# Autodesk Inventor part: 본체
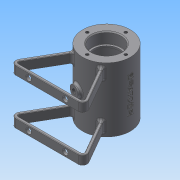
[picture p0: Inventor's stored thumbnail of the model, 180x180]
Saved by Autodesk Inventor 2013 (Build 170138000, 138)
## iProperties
Created: 2016-03
Part Number: 본체
Material: 일반
Document SubType Name: Modeling
Designer: Administrator
Density: 1 g/cm^3
Author: Administrator
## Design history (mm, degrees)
sketch "스케치1"
  geometry: C1 r 26 at (0, 0); 1 further point
  constraints: 1 centre point, 1 coincident
  dimensions: "d0" = 52 diameter of C1
extrude "돌출1" new body sketch "스케치1" stored distance "d1" = 70; taper "d2" = 0 deg
node "작업 평면1"
sketch "스케치3"
  geometry: L1 (0, -65)-(33.934, -65); L2 (0, -65)-(-33.934, -65); L3 (-16.613, -20)-(-38.264, -57.5); L4 (16.613, -20)-(38.264, -57.5); L5 (35.666, -59)-(15.685, -24.392); L6 (-15.685, -24.392)-(-35.666, -59); L7 (-33.934, -62)-(0, -62); L8 (0, -62)-(33.934, -62); L9 (15.685, -24.392)-(14.183, -21.791); L10 (-15.685, -24.392)-(-14.183, -21.791); A1 r 26 centre (0, 0) between (16.613, -20) and (-16.613, -20) reference; A2 r 5 centre (-33.934, -60) between (-38.264, -57.5) and (-33.934, -65); A3 r 5 centre (33.934, -60) between (33.934, -65) and (38.264, -57.5); A4 r 2 centre (-33.934, -60) between (-35.666, -59) and (-33.934, -62); A5 r 2 centre (33.934, -60) between (33.934, -62) and (35.666, -59); A6 r 26 centre (0, 0) between (-16.613, -20) and (-14.183, -21.791); A7 r 26 centre (0, 0) between (14.183, -21.791) and (16.613, -20); 3 further points
  constraints: 20 end point, 14 point on circle, 6 centre point, 4 collinear, 4 point on line, 4 tangent, 1 coincident, 1 equal radius, 4 other
  dimensions: "d33" = 45 vertical distance of point (42.594, -65) L4.start; "d34" = 45 vertical distance of point (-42.594, -65) L3.start; "d37" = 5 radius of A2; "d38" = 3 distance between parallel lines of L4 L5
extrude "돌출2" join sketch "스케치3" distance "d39" = 10; taper "d40" = 0 deg
sketch "스케치4"
  geometry: C1 r 26 at (0, 0) reference; C2 r 16 at (0, 0)
  constraints: 1 centre point, 1 coincident
  dimensions: "d41" = 32 diameter of C2
extrude "돌출3" cut sketch "스케치4" distance "d42" = 12; taper "d43" = 0 deg
sketch "스케치5"
  geometry: C1 r 16 at (0, 0) reference; C2 r 14 at (0, 0)
  constraints: 1 centre point, 1 coincident
  dimensions: "d44" = 28 diameter of C2
extrude "돌출4" cut sketch "스케치5" distance "d45" = 2; taper "d46" = 0 deg
sketch "스케치6"
  geometry: L1 (0, 0)-(0, 21); C1 r 26 at (0, 0) reference
  constraints: 2 end point, 1 coincident, 1 vertical alignment, 2 other
hole "구멍1" sketch "스케치6" at (0, 21) diameter "d48" = 3.242; stored, may be unused: countersink angle "d52" = 90 deg, drill point angle "d54" = 118 deg; dims "d49" = 8, "d50" = 4, "d51" = 2, "d53" = 10
node "작업 평면2"
sketch "스케치7"
  geometry: C1 r 21 at (0, 0); 1 further point
  constraints: 1 centre point, 1 coincident
  dimensions: "d58" = 42 diameter of C1
extrude "돌출5" cut sketch "스케치7" stored distance "d59" = 42; taper "d60" = 0 deg
sketch "스케치8"
  geometry: L1 (0, 0)-(67.868, 0) reference; L2 (67.868, -10)-(0, -10) reference; L3 (33.934, -10)-(33.934, -5); C1 r 3 at (53.934, -5); C2 r 3 at (13.934, -5); 1 further point
  constraints: 2 centre point, 2 end point, 1 midpoint, 1 perpendicular
  dimensions: "d63" = 6 diameter of C1; "d65" = 6 diameter of C2
extrude "돌출6" cut sketch "스케치8" distance "d66" = 20; taper "d67" = 0 deg
node "작업 평면3"
sketch "스케치9"
  geometry: L1 (26, 35)-(-26, 35) reference; L2 (0, 35)-(0, 0); C1 r 5 at (0, 0)
  constraints: 2 end point, 1 centre point, 1 coincident, 1 midpoint, 1 perpendicular
  dimensions: "d69" = 35 distance of L2.start L2.end (derived); "d70" = 10 diameter of C1
extrude "돌출7" join sketch "스케치9" stored distance "d71" = 20; taper "d72" = 0 deg
sketch "스케치10"
  geometry: C1 r 5 at (0, 0) reference
hole "구멍2" sketch "스케치10" at (0, 0) diameter "d73" = 5.188; stored, may be unused: countersink angle "d77" = 90 deg, drill point angle "d79" = 118 deg; dims "d74" = 8, "d75" = 4, "d76" = 2, "d78" = 10
sketch "스케치11"
  geometry: L1 (0, 0)-(0, -44.243); L2 (0, 0)-(-7.506, -28.012)
  constraints: 4 end point, 1 vertical
  dimensions: "d80" = 29 distance of L1.start L2.end; "d81" = 15 deg angle of L1 L2
node "작업 평면4"
sketch "스케치12"
  geometry: C1 r 6 at (0, 0); 1 further point
  constraints: 1 centre point, 1 coincident
  dimensions: "d82" = 12 diameter of C1
extrude "돌출8" join sketch "스케치12" stored distance "d83" = 20; taper "d84" = 0 deg
sketch "스케치13"
  geometry: C1 r 6 at (0, 0) reference
hole "구멍3" sketch "스케치13" at (0, 0) diameter "d85" = 5.188; stored, may be unused: countersink angle "d89" = 90 deg, drill point angle "d91" = 118 deg; dims "d86" = 8, "d87" = 4, "d88" = 2, "d90" = 10
node "작업 평면5"
sketch "스케치14"
  geometry: L1 (26, 35)-(-26, 35) reference; 2 further points
  constraints: 1 other
feature "엠보싱1" sketch "스케치14" dims "d33" = 45, "d34" = 45, "d37" = 5, "d38" = 3, "d95" = 0.5, "d96" = 0
chamfer "모따기1" distance "d97" = 1; stored, may be unused: second distance "d98" = 2, angle "d99" = 45 deg
fillet "모깎기2" dims "d102" = 0.5, "d103" = 0.3, "d104" = 3, "d105" = 2
node "솔리드1"
pattern_circular "원형 패턴1" dims angle "d56" = 360 deg
mirror "대칭1"
mirror "대칭2"
other parameters: "d68" = 29, "d92" = 45.25
